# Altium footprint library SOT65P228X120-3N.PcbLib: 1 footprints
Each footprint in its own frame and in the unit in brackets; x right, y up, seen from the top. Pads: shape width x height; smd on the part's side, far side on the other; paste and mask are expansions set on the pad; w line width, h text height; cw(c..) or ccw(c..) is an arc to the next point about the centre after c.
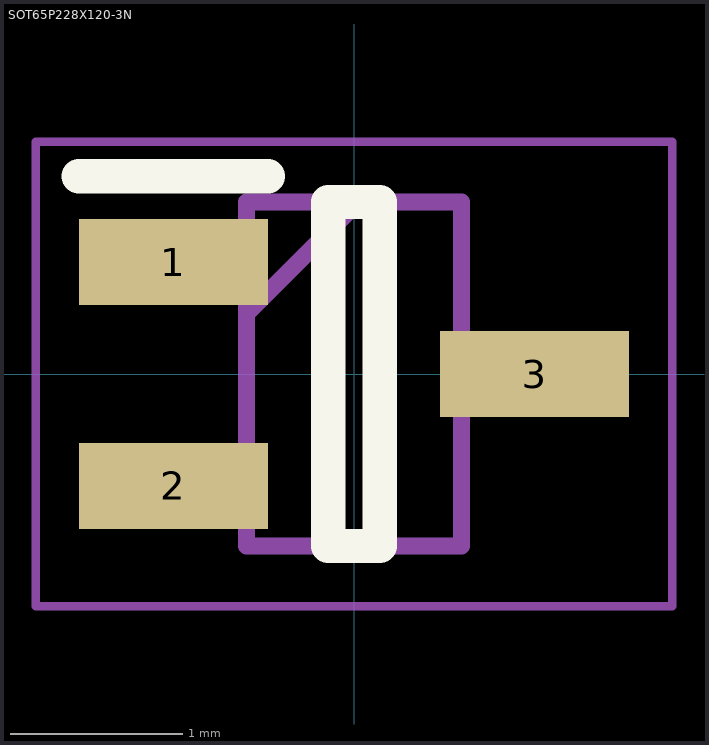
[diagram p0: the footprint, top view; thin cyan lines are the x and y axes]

## SOT65P228X120-3N [mm]
pads (3):
  rect 1.1x0.5 smd: 1(-1.05,0.65) 2(-1.05,-0.65) 3(1.05,0)
Top Overlay:
  lines w0.2: -1.6,1.15 -0.5,1.15 ; -0.15,-1 0.15,-1 0.15,1 -0.15,1 -0.15,-1
Mechanical 15:
  lines w0.1: -0.625,0.35 0.025,1 ; -0.625,-1 0.625,-1 0.625,1 -0.625,1 -0.625,-1
Mechanical 20:
  lines w0.05: -1.85,-1.35 1.85,-1.35 1.85,1.35 -1.85,1.35 -1.85,-1.35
